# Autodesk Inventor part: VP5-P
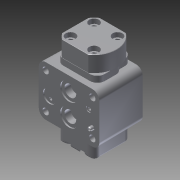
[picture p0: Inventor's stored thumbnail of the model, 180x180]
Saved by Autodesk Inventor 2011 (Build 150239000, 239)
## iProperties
Created: 2012-01
Part Number: VP5-P
Document SubType Name: Modeling
Designer: khramov
Density: 1 g/cm^3
Author: khramov
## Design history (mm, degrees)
derived "VP5_P2_MU_12.iam"
node "Твердое тело1"
node "0110727_.ipt:1"
node "0111485_.ipt:1"
sketch "0530079_UNI_5931___M10x25.ipt:1"
sketch "0530079_UNI_5931___M10x25.ipt:2"
sketch "0530079_UNI_5931___M10x25.ipt:3"
sketch "0530079_UNI_5931___M10x25.ipt:4"
node "0110728_.ipt:1"
sketch "0530079_UNI_5931___M10x25.ipt:5"
sketch "0530079_UNI_5931___M10x25.ipt:6"
sketch "0530079_UNI_5931___M10x25.ipt:7"
sketch "0530079_UNI_5931___M10x25.ipt:8"
sketch "3001050000_.ipt:1"
sketch "0550326_DIN_1481_6x16.ipt:1"
